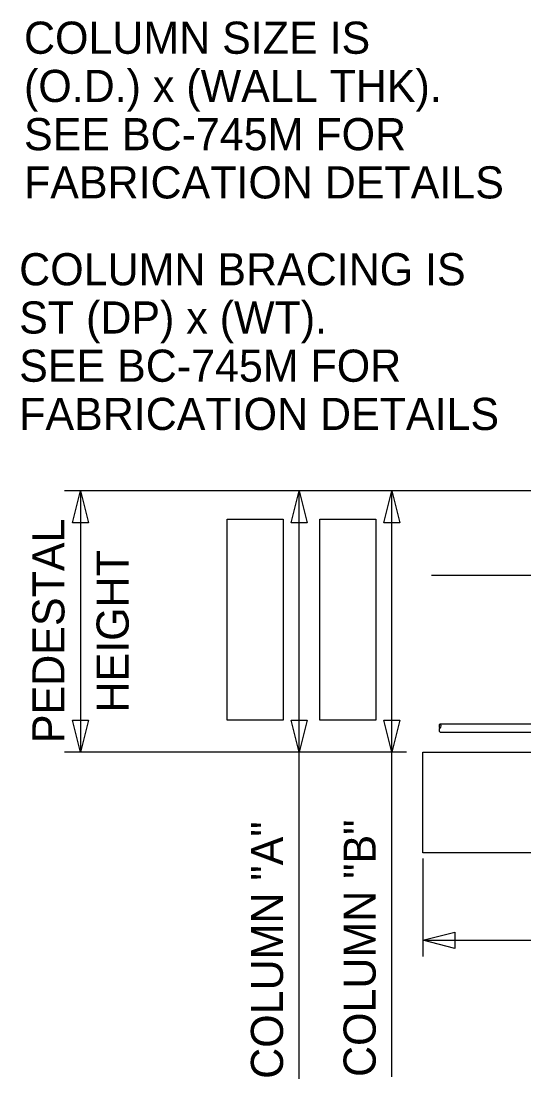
# Model space of a CAD drawing. Extents: x 3831399 to 3833095, y 499014 to 500202.
# Drawn here: x 3832848.3 to 3832893.8, y 499771 to 499866.8 of the extents above; entities that cross this region are included whole.
import ezdxf

# ---------------------------------------------------------------- set-up
doc = ezdxf.new("R2010")
doc.units = 0
for name, color, linetype in [('0-foundation', 7, 'Continuous'), ('Default', 7, 'Continuous'), ('DIM TXT', 7, 'Continuous'), ('XEG', 7, 'Continuous')]:
    doc.layers.add(name, color=color, linetype=linetype)

msp = doc.modelspace()

# ---------------------------------------------------------------- linework, layer by layer
at = {"layer": '0-foundation'}
for p, q in [((3832886.24, 499803.172), (3832912.413, 499803.172)), ((3832886.24, 499802.414), (3832912.413, 499802.414)), ((3832884.666, 499791.503), (3832884.666, 499800.602)), ((3832884.666, 499800.602), (3832913.669, 499800.602)), ((3832989.306, 499791.503), (3832884.666, 499791.503))]:
    msp.add_line(p, q, dxfattribs=at)
for centre, start, end in [((3832886.382, 499802.983), 126.8699, 233.1301), ((3832886.382, 499802.604), 126.8699, 233.1301), ((3832886.097, 499802.983), 306.8699, 53.1301)]:
    msp.add_arc(centre, 0.237, start, end, dxfattribs=at)
at = {"layer": 'Default'}
for p, q in [((3832866.948, 499803.502), (3832866.948, 499821.689)), ((3832866.948, 499821.689), (3832872.04, 499821.689)), ((3832872.04, 499821.689), (3832872.04, 499803.502)), ((3832875.336, 499803.502), (3832875.336, 499821.689)), ((3832875.336, 499821.689), (3832880.428, 499821.689)), ((3832880.428, 499821.689), (3832880.428, 499803.502)), ((3832872.04, 499803.502), (3832866.948, 499803.502)), ((3832880.428, 499803.502), (3832875.336, 499803.502))]:
    msp.add_line(p, q, dxfattribs=at)
at = {"layer": 'DIM TXT'}
for p, q in [((3832912.594, 499824.277), (3832852.222, 499824.277)), ((3832853.677, 499824.277), (3832853.677, 499800.602)), ((3832889.87, 499824.274), (3832872.018, 499824.274)), ((3832873.473, 499800.602), (3832873.473, 499824.274)), ((3832911.139, 499824.277), (3832880.407, 499824.277)), ((3832881.862, 499800.602), (3832881.862, 499824.277)), ((3832883.211, 499800.602), (3832852.222, 499800.602)), ((3832883.211, 499800.602), (3832872.018, 499800.602)), ((3832873.473, 499771.042), (3832873.473, 499800.602)), ((3832883.211, 499800.602), (3832880.407, 499800.602)), ((3832881.862, 499771.211), (3832881.862, 499800.602)), ((3832884.666, 499790.975), (3832884.666, 499782.125)), ((3832884.666, 499783.58), (3832989.306, 499783.58))]:
    msp.add_line(p, q, dxfattribs=at)
for points in [[(3832852.95, 499821.367), (3832853.677, 499824.277), (3832854.405, 499821.367)], [(3832872.746, 499821.364), (3832873.473, 499824.274), (3832874.201, 499821.364)], [(3832881.134, 499821.367), (3832881.862, 499824.277), (3832882.589, 499821.367)], [(3832854.405, 499803.512), (3832853.677, 499800.602), (3832852.95, 499803.512)], [(3832874.201, 499803.512), (3832873.473, 499800.602), (3832872.746, 499803.512)], [(3832882.589, 499803.512), (3832881.862, 499800.602), (3832881.134, 499803.512)], [(3832887.576, 499782.852), (3832884.666, 499783.58), (3832887.576, 499784.307)]]:
    msp.add_lwpolyline(points, close=True, dxfattribs=at)
at = {"layer": 'XEG'}
msp.add_line((3832885.468, 499816.637), (3833002.213, 499816.637), dxfattribs=at)

# ---------------------------------------------------------------- texts
at = {"layer": 'DIM TXT'}
for s, p in [('COLUMN SIZE IS', (3832848.561, 499863.829)), ('(O.D.) x (WALL THK).', (3832848.561, 499859.464)), ('SEE BC-745M FOR', (3832848.561, 499855.099)), ('FABRICATION DETAILS', (3832848.561, 499850.734)), ('COLUMN BRACING IS', (3832848.124, 499842.87)), ('ST (DP) x (WT).', (3832848.124, 499838.505)), ('SEE BC-745M FOR', (3832848.124, 499834.14)), ('FABRICATION DETAILS', (3832848.124, 499829.775))]:
    msp.add_text(s, height=2.90992, dxfattribs=at).set_placement(p)
for s, p in [('PEDESTAL', (3832852.222, 499801.43)), ('HEIGHT', (3832858.042, 499804.203)), ('COLUMN "A"', (3832872.018, 499771.042)), ('COLUMN "B"', (3832880.407, 499771.211))]:
    msp.add_text(s, height=2.9099, rotation=90, dxfattribs=at).set_placement(p)

doc.saveas('drawing.dxf')
